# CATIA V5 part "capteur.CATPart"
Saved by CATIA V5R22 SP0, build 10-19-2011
Part number: Part23
Bounding box of the stored display mesh (mm): x 0 to 10, y 0 to 10, z 0 to 15
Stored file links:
  D:\PER\CAO_PER_MODIF_2025\CAO_PER_pick&place_2024P\Sous_Ensemble_Flacon\capteur.CATPart
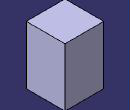
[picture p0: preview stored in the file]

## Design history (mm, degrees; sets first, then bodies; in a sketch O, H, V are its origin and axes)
Body1 (main body)
  Sketch1 on yz-plane, origin (0, 0, 0), H (0, 1, 0), V (0, 0, 1)
    line L1 (0, 0) -> (10, 0)
    line L2 (10, 0) -> (10, 15)
    line L3 (10, 15) -> (0, 15)
    line L4 (0, 15) -> (0, 0)
    point P1 (10, 0)
    point P2 (10, 15)
    point P3 (0, 15)
    distance P2 P3 = 10
    distance P2 P1 = 15
    horizontal: L1 H, L3 H
    vertical: L2 V, L4 V
  Pad1: profile Sketch1, direction (1, 0, 0), length 10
